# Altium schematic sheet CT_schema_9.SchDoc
size 277 x 170 mm
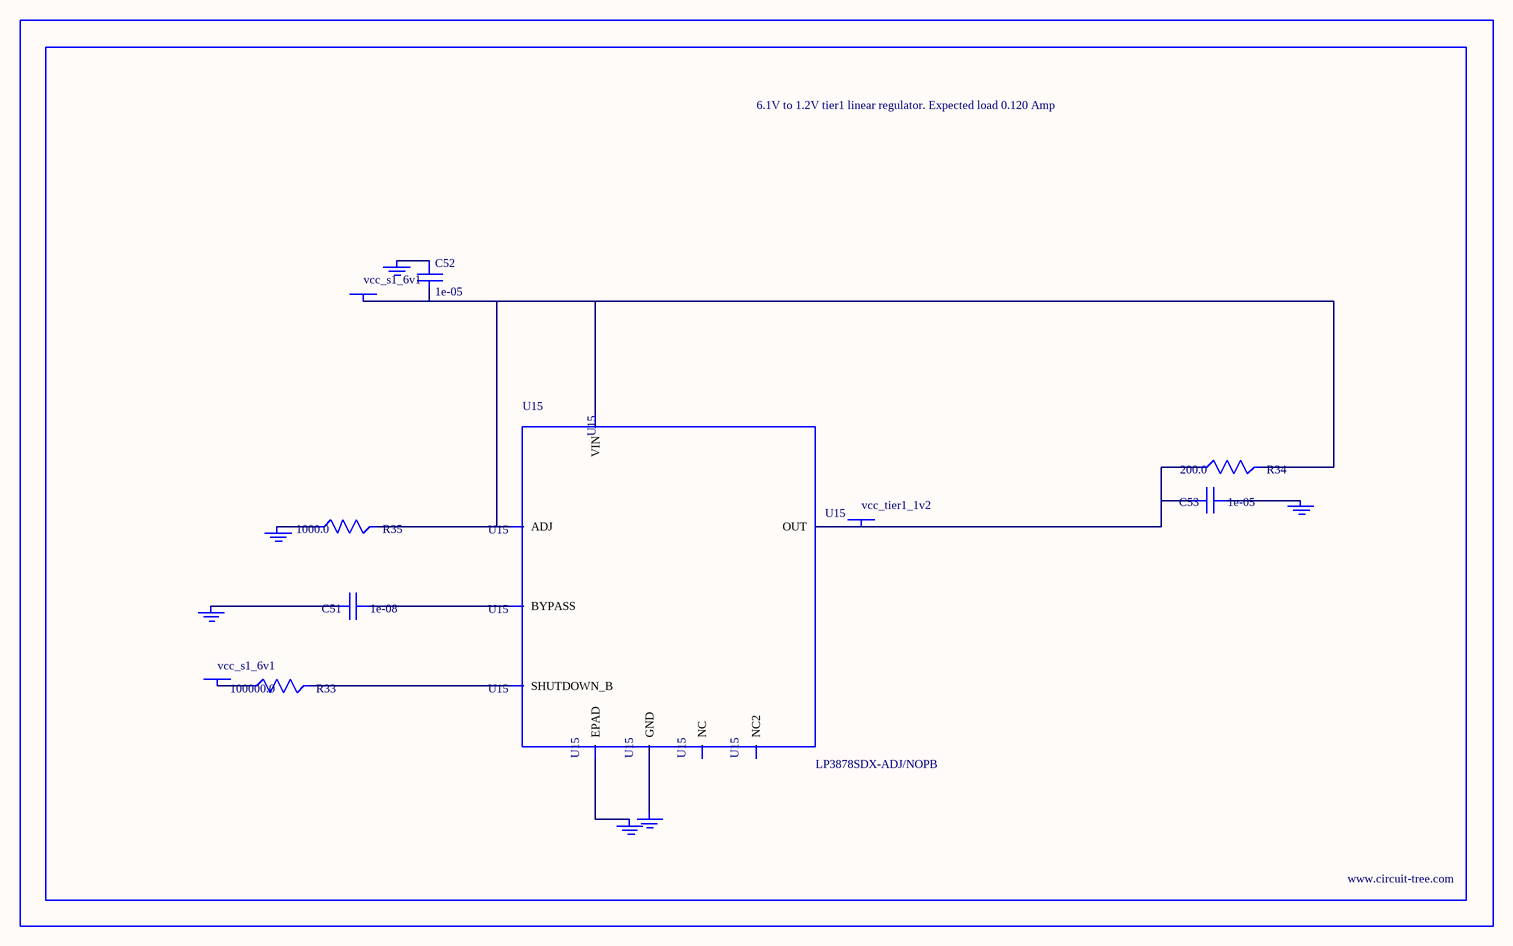
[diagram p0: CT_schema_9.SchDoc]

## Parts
BORDER8  (no value)
C51  1e-08  [C0402]
C52  1e-05  [C1206]
C53  1e-05  [C0805]
GND_INSTANCE_8_0  (no value)
GND_INSTANCE_8_1  (no value)
GND_INSTANCE_8_2  (no value)
GND_INSTANCE_8_3  (no value)
GND_INSTANCE_8_4  (no value)
GND_INSTANCE_8_5  (no value)
POWER_INSTANCE_8_0  vcc_s1_6v1
POWER_INSTANCE_8_1  vcc_s1_6v1
POWER_INSTANCE_8_2  vcc_tier1_1v2
R33  100000.0  [R0603]
R34  200.0  [R0603]
R35  1000.0  [R0603]
U15  LP3878SDX-ADJ/NOPB  [WSON-8]

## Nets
NetC51_1: C51.1 U15.1(BYPASS)
NetC51_2: C51.2 GND_INSTANCE_8_0.0(GND)
NetC52_1: C52.1 GND_INSTANCE_8_1.0(GND)
NetC52_2: C52.2 POWER_INSTANCE_8_0.0(PWR) R34.2 R35.2 U15.4(VIN) U15.6(ADJ)
NetC53_1: C53.1 GND_INSTANCE_8_2.0(GND)
NetC53_2: C53.2 POWER_INSTANCE_8_2.0(PWR) R34.1 U15.5(OUT)
NetGND_INSTANCE_8_3_0: GND_INSTANCE_8_3.0(GND) R35.1
NetGND_INSTANCE_8_4_0: GND_INSTANCE_8_4.0(GND) U15.PAD(EPAD)
NetGND_INSTANCE_8_5_0: GND_INSTANCE_8_5.0(GND) U15.3(GND)
NetPOWER_INSTANCE_8_1_0: POWER_INSTANCE_8_1.0(PWR) R33.1
NetR33_2: R33.2 U15.8(SHUTDOWN_B)

Not connected (* = marked no-connect by the designer): U15 2(NC) 7(NC2)

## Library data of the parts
BORDER8 = BORDER_PAGE8
C51 = C0402C103K3RAC
C52 = C1206C106K3RACTU
C53 = GRM219R60J106ME19D
GND_INSTANCE_8_0-GND_INSTANCE_8_5 = GND
POWER_INSTANCE_8_0-POWER_INSTANCE_8_2 = PWR
R33 = RC0603JR-07100KL
R34 = RC0603JR-07200RL
R35 = RC0603JR-071KL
